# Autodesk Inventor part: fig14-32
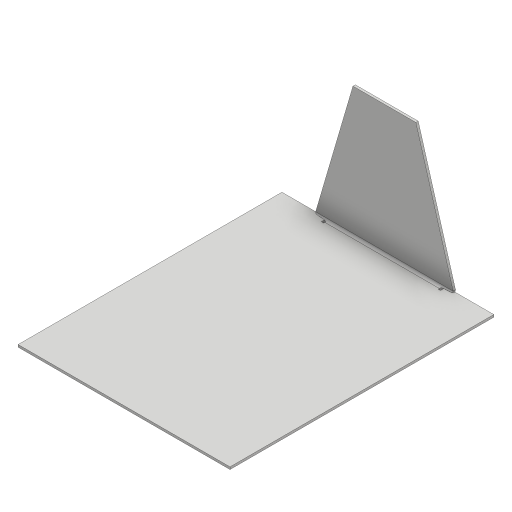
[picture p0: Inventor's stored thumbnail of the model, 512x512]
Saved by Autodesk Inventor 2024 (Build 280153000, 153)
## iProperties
Created: 2017-05
Part Number: fig14-32
Material: Generic
Document SubType Name: Sheet Metal
Designer: CADCIM 00
Density: 1 g/cm^3
Sheet Metal Rule: Default_mm
Appearance: Default
Author: CADCIM 00
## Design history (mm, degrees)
node "Face1"
  sketch "Sketch1"
    geometry: L1 (0, 0)-(45.552, 0); L2 (45.552, 0)-(45.552, 56.721); L3 (45.552, 56.721)-(0, 56.721); L4 (0, 56.721)-(0, 0)
    constraints: 8 end point, 2 parallel, 1 horizontal, 1 perpendicular
node "Face2"
  sketch "Sketch2"
    geometry: L1 (10.232, -9.455)-(15.772, -28.394); L2 (15.772, -28.394)-(29.3, -28.394); L3 (29.3, -28.394)-(34.84, -9.455); L4 (34.84, -9.455)-(10.232, -9.455); 1 further point
    constraints: 8 end point, 1 horizontal, 1 parallel
body "Solid1"
face "Plate1" dims "d0" = 0.5 (= Thickness)
face "Plate2" dims "d0" = 0.5 (= Thickness), "d1" = 0.5 (= BendRadius), "d2" = 0.5 (= BendReliefWidth), "d4" = 1 (= MinimumRemnant)
bend "Bend1" dims "d0" = 0.5 (= Thickness), "d1" = 0.5 (= BendRadius), "d2" = 0.5 (= BendReliefWidth), "d3" = 0.25 (= BendReliefDepth), "d4" = 1 (= MinimumRemnant), "d5" = 0.5 (= TransitionRadius), "SeamGap" = 0.01
other parameters: "Thickness" = 0.5, "BendRadius" = 0.5 (= Thickness), "BendReliefWidth" = 0.5 (= Thickness), "BendReliefDepth" = 0.25 (= 0.5 x Thickness), "CornerReliefSize" = 2 (= 4 x Thickness), "MinimumRemnant" = 1 (= 2 x Thickness), "TransitionRadius" = 0.5 (= BendRadius), "JacobiRadiusSize" = 0.5 (= BendRadius), "GapSize" = 0.5 (= Thickness)
